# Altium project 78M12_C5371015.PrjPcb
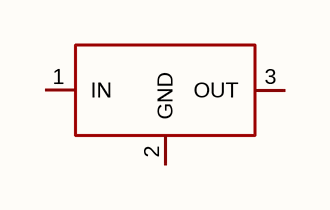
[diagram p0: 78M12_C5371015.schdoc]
1 sheet, 1 parts. Net scope: global (net labels, ports and power ports of the same name join across sheets).

## Sheet 78M12_C5371015.schdoc
size 127 x 101 mm

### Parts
U?  78m12_c5371015  [TO-252-3_L6.6-W6.1-P4.57-LS9.9-BR-CW]  (value not drawn)

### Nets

Not connected (* = marked no-connect by the designer): U? 1(IN) 2(GND) 3(OUT)

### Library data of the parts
U? = 78m12_c5371015: 输出极性:正极;工作电压:30V;输出电压:12V;输出电流:500mA;电源纹波抑制比(PSRR):80dB@(120Hz);输出类型:固定;; Manufacturer: TECH PUBLIC(台舟); ManufacturerPart: 78M12; AddInBom: yes; ModelId: dee852f3c6b348a2b9d5be5dd3244081; ModelTransform: 258.97184,390.1567,0,90,0,0,-35.433,0,0; Output Configuration: 正极; Voltage - Supply: 30V; Output Voltage: 12V; Output Current: 500mA; Voltage Dropout: 2V@(1A); standby current: 6mA; Noise: 75uV; Output Type: 固定; Number of Outputs: 1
